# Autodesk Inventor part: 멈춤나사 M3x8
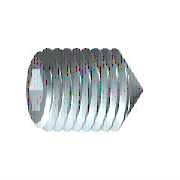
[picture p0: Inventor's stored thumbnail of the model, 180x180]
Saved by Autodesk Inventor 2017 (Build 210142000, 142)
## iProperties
IsCustomPart: 1
Created: 2012-02
Part Number: 멈춤나사 M3x8
Material: 강철, 연강
Description: 6각 소켓 머리 없는 멈춤 나사
Document SubType Name: Modeling
Standard: KS B 1028
Designer: test
Standards Organization: KS
Language: ko-KR
Size Designation: 원추점 M3x8
Categories: <MemberInstance><Categories><Category DisplayName="조임쇠" InternalName="e4da775c-781d-43d5-af7c-5136215cf5a6" Mnemonic="FSTN"><Category DisplayName="볼트" InternalN
Density: 1 g/cm^3
Appearance: 강철
Author: test
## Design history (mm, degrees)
sketch "스케치1"
  geometry: L1 (0, 0)-(5.5, 0); L2 (8, 0.866)-(8, 1.5); L3 (8, 1.5)-(0, 1.5); L4 (8, 0.866)-(6, 0.866); L5 (6, 0.866)-(5.5, 0); L6 (0, -0.3)-(0, 1.8) reference; L7 (0, 1.5)-(0, 0)
  constraints: 13 end point, 3 parallel, 1 collinear, 1 perpendicular, 1 point on line
  dimensions: "d0" = 2 distance of L2.start L4.end (= INTI); "d1" = 60 deg angle of L5 L1; "d2" = 3 diameter of L3 L1 (= NND); "d3" = 1.73205 diameter of L4 L1 (= 1.1547 x SW); "d5" = 8 distance from line of L2 L3.end (= NLG)
revolve "본체" sketch "스케치1" stored, may be unused: angle "d6" = 90 deg
sketch "스케치2"
  geometry: L1 (-0.433, 0.75)-(0.433, 0.75); L2 (0.433, 0.75)-(0.866, 0); L3 (0.866, 0)-(0.433, -0.75); L4 (0.433, -0.75)-(-0.433, -0.75); L5 (-0.433, -0.75)-(-0.866, 0); L6 (-0.866, 0)-(-0.433, 0.75); 3 further points
  constraints: 12 end point, 1 coincident, 1 horizontal, 13 other
extrude "슬롯" join sketch "스케치2" taper "d7" = 0 deg; stored distance "d21" = 10
workaxis "Work Axis1"
workplane "Work Plane1"
sketch "스케치4"
  geometry: L1 (0, 0.15)-(-1.35, 1.5) reference; L2 (0, -0.15)-(-1.35, -1.5) reference; L3 (-1.35, -1.5)-(0.15, 0); L4 (-1.35, 1.5)-(0.15, 0); 2 further points
  constraints: 4 end point, 1 coincident, 1 collinear, 1 horizontal alignment
node "작업점1"
body "Solid1"
feature "스레드" dims "d12" = 8 (= NLG), "d13" = 0
chamfer "모따기1" distance "d8" = 1.35 (computed from NND, SPD, FAWI); stored, may be unused: angle "d9" = 45 deg (= FAWI), second distance "d34" = 1.35 (computed from NND, SPD, FAWI)
chamfer "모따기2" distance "d10" = 0.30673 (= -0.5 x GD1 + 0.5 x NND); stored, may be unused: angle "d11" = 45 deg (= FAWI), second distance "d35" = 0.30673 (= -0.5 x GD1 + 0.5 x NND)
other parameters: "NND" = 3 [user parameter; used in 5 equation terms], "NLG" = 8 [user parameter; used in 2 equation terms], "INTI" = 2 [user parameter; used in 1 equation term], "FAWI" = 45 deg [user parameter; used in 4 equation terms], "SW" = 1.5 [user parameter; used in 2 equation terms], "GD1" = 2.38655 (= THREADDIA - 1.2269 x PTC) [user parameter; used in 2 equation terms], "d4" = 0, "FAWI1" = 45 deg [user parameter], "SPD" = 0.3 [user parameter; used in 2 equation terms], "d36" = 0, "d37" = 0, "GUL" = 0.30673 (= 0.61345 x PTC) [user parameter], "TOA" = 30 deg [user parameter], "THREADDIA" = 3 [user parameter; used in 1 equation term], "PTC" = 0.5 [user parameter; used in 4 equation terms], "GAL" = 0.30673 (= 0.61345 x PTC) [user parameter], "E0" = 1.7325 (= 1.155 x SW) [user parameter]
